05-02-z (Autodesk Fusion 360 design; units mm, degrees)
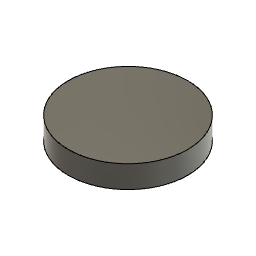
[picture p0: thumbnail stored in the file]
sketch "スケッチ1" plane through (0, 0, 0) normal (0, 0, 1) x axis (1, 0, 0)
  line L1 (-7, -2) -> (-8, -2)
  line L2 (-7, 0) -> (-7, -2)
  line L3 (-8, 0) -> (-7, 0)
  line L4 (-8, -2) -> (-8, 0)
  line L5 (0, 22.5) -> (0, 1.75)
  point P1 (0, 0)
  point P4 (-7, 0)
  point P2 (-8, -2)
  point P3 (-7, -2)
  point P5 (-8, 0)
  horizontal L1
  vertical L2
  horizontal L3
  vertical L4
  horizontal P1 P4
  dimension "d1" distance P2 P3 = 1
  dimension "d2" distance P2 P5 = 2
  dimension "d3" = 16
revolve "回転1" sketch "スケッチ1" AlongAngle 360
sketch "スケッチ2" plane through (0, 0, 0) normal (0, 0, 1) x axis (1, 0, 0)
  line L1 (-8, 0) -> (0, 0)
  line L2 (-8, 1) -> (-8, 0)
  line L3 (0, 1) -> (-8, 1)
  line L4 (0, 0) -> (0, 1)
  line L5 (-8, -2) -> (-8, 0)
  line L6 (8, 0) -> (8, -2)
  point P1 (0, 0)
  point P2 (0, 0)
  point P3 (-8, 0)
  point P4 (-8, 1)
  horizontal L1
  vertical L2
  horizontal L3
  vertical L4
  coincident P1 P2
  collinear L2 L5
  dimension "d5" distance P3 P4 = 1
revolve "回転2" sketch "スケッチ2" AlongAngle 360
